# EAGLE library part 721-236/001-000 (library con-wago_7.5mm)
Serie 721, Stiftleiste (für Leiterplatten) Einlötstift gerade 1 x 1 mm / Series 721, Male header (for PCBs) Straight solder pin 1 x 1 mm Polzahl / Pole No.: 6 Rastermaß / Pitch: 7.5 mm Bemessungsspannung / Rated Voltage: 630 V Nennstrom / Nominal Current: 12 A Lötstiftlänge: / Solder Pin Length: 5 mm Farbe / Color: lichtgrau / light gray Stand: 01.01.2012. Die jeweils aktuellen Daten zu diesem Artikel finden Sie in unserem Produktkatalog, den Sie unter www.wago.com einsehen können. As of: 01/01/2012. Please find the newest data for this article in our product catalogue, which can be viewed under www.wago.com.
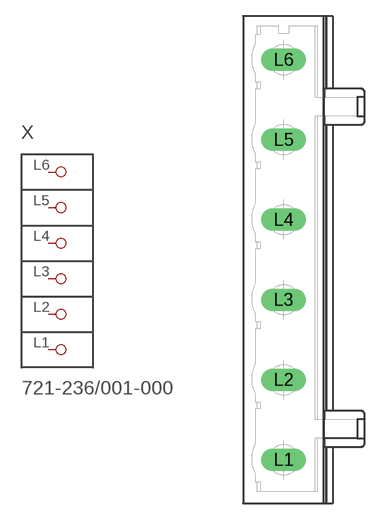
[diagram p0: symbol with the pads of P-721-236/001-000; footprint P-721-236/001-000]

Designator prefix X

## 721-236/001-000  [P-721-236/001-000]
L1  P1
L2  P2
L3  P3
L4  P4
L5  P5
L6  P6

## Footprint P-721-236/001-000 (pad centres in mm)
drill 1.4 long: L1 -1.9,-18.75; L2 -1.9,-11.25; L3 -1.9,-3.75; L4 -1.9,3.75; L5 -1.9,11.25; L6 -1.9,18.75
